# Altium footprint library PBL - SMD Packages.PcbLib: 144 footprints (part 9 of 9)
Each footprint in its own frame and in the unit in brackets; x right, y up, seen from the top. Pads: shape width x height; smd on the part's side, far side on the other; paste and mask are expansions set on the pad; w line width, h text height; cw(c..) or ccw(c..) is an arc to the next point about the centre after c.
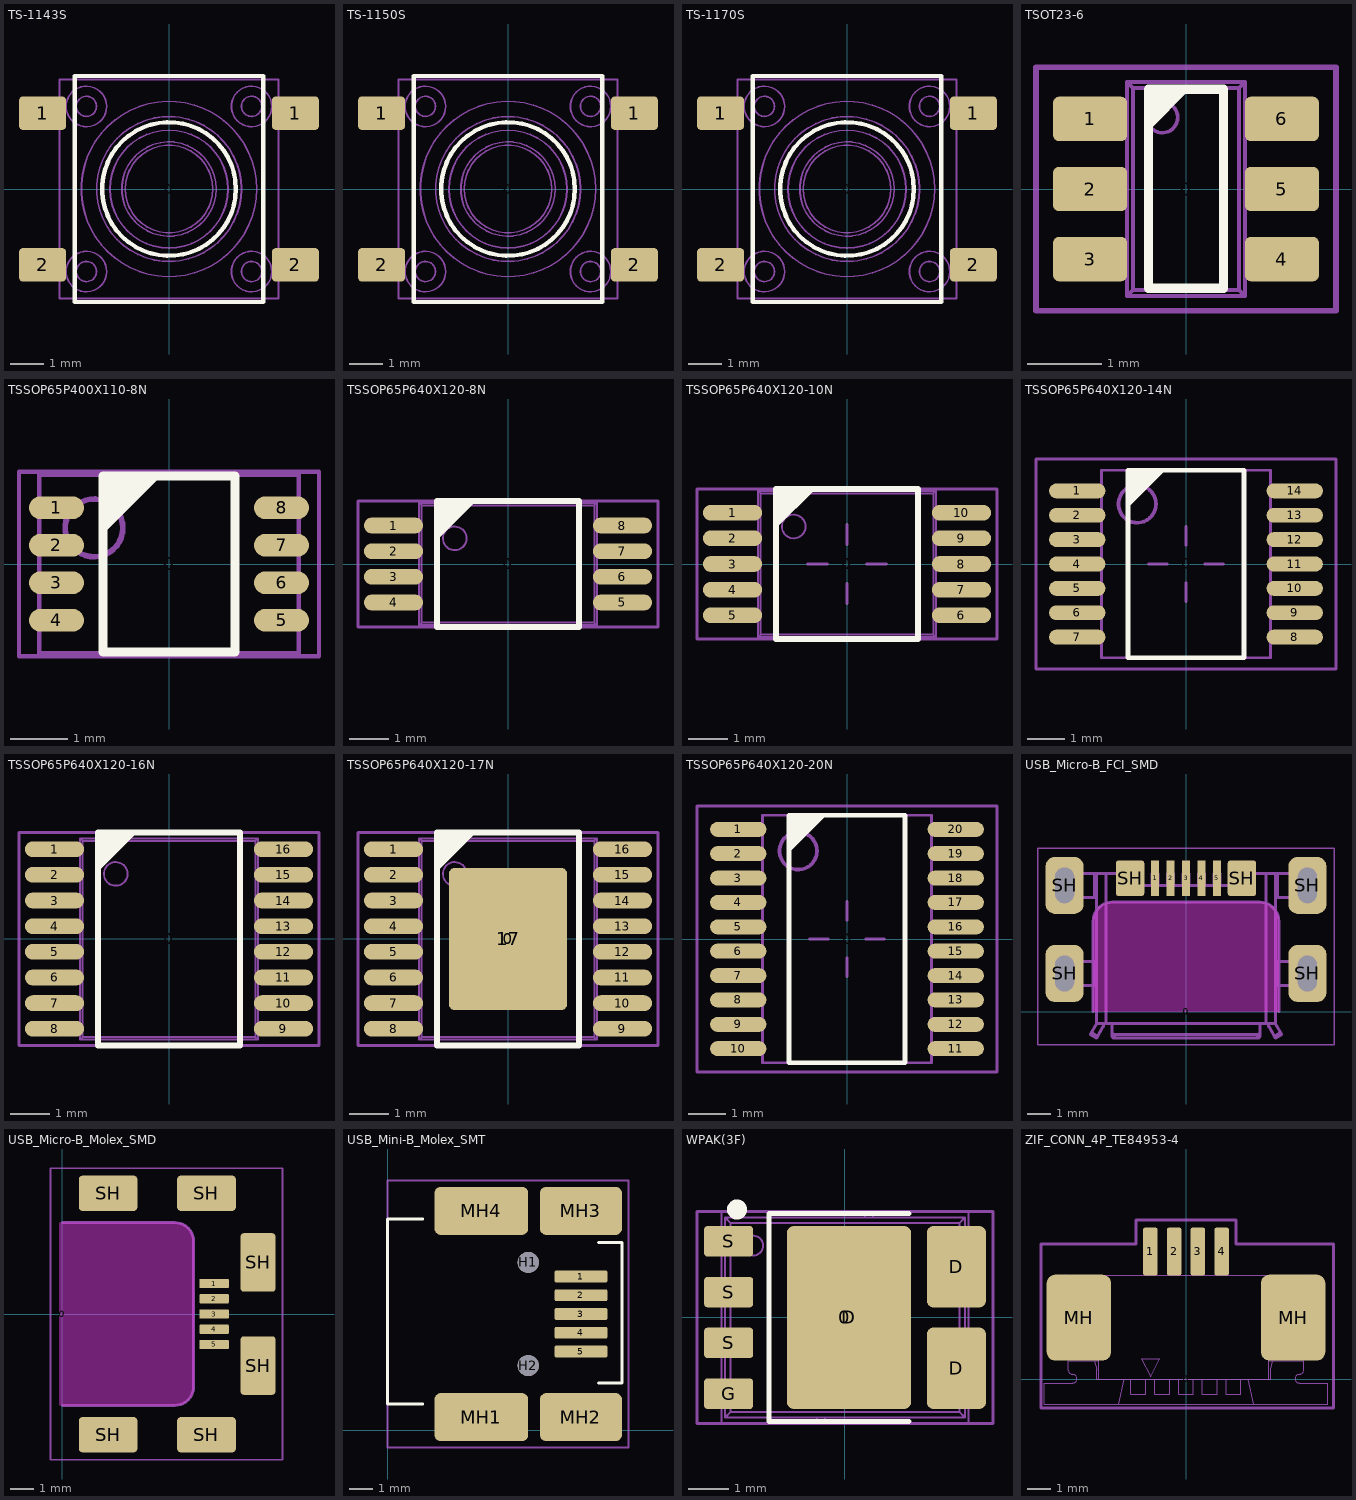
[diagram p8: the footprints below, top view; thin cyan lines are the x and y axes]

## TS-1143S [mm] "6.5x6.5mm SMD tact switch 4.3mm stem"
height 4.3
pads (5):
  round 0.508 on Mech15: 0(0,0)
  rrect25% 1.4x1 smd: 1(-3.75,2.25) 1(3.75,2.25) 2(-3.75,-2.25) 2(3.75,-2.25)
Top Overlay:
  circle w0.127: c0,0 r1.984
  lines w0.127: -2.794,-3.35 -2.794,3.35 2.794,3.35 2.794,-3.35 -2.794,-3.35
13 - 3D Top Side:
  circle w0.05: c0,0 r1.4
  circle w0.05: c0,0 r1.3
  circle w0.05: c0,-0.002 r1.75
  circle w0.05: c0,0 r2.15
  circle w0.05: c0,0 r2.6
  circle w0.05: c2.45,2.452 r0.3
  circle w0.05: c-2.45,2.452 r0.3
  circle w0.05: c2.45,-2.448 r0.3
  circle w0.05: c-2.45,-2.448 r0.3
  circle w0.05: c-2.45,2.45 r0.6
  circle w0.05: c2.45,2.45 r0.6
  circle w0.05: c2.45,-2.45 r0.6
  circle w0.05: c-2.45,-2.45 r0.6
  lines w0.05: -3.591,-2.6 -3.591,-1.9 ; -3.591,1.9 -3.591,2.6 ; -3.571,-2.6 -3.571,-1.9 ; -3.571,1.9 -3.571,2.6 ; -3.468,-2.6 -3.468,-1.9 ; -3.468,1.9 -3.468,2.6 ; -3.253,-2.6 -3.253,-1.9 ; -3.253,1.9 -3.253,2.6 ; -3.25,-2.6 -4,-2.6 -4,-1.9 -3.25,-1.9 ; -3.25,1.9 -4,1.9 -4,2.6 -3.25,2.6 ; 3.25,-2.6 4,-2.6 4,-1.9 3.25,-1.9 ; 3.25,1.9 4,1.9 4,2.6 3.25,2.6 ; 3.253,-2.6 3.253,-1.9 ; 3.253,1.9 3.253,2.6 ; 3.468,-2.6 3.468,-1.9 ; 3.468,1.9 3.468,2.6 ; 3.571,-2.6 3.571,-1.9 ; 3.571,1.9 3.571,2.6 ; 3.591,-2.6 3.591,-1.9 ; 3.591,1.9 3.591,2.6 ; -3.25,-3.25 3.25,-3.25 3.25,3.25 -3.25,3.25 -3.25,-3.25
3D body "TS-1143S-WP.STEP": height 4.3, standoff 0, extent -4,-3.25 4,3.25

## TS-1150S [mm] "6.5x6.5mm SMD tact switch 5.0mm stem"
height 5
pads (5):
  round 0.508 on Mech15: 0(0,0)
  rrect25% 1.4x1 smd: 1(-3.75,2.25) 1(3.75,2.25) 2(-3.75,-2.25) 2(3.75,-2.25)
Top Overlay:
  circle w0.127: c0,0 r1.984
  lines w0.127: -2.794,-3.35 -2.794,3.35 2.794,3.35 2.794,-3.35 -2.794,-3.35
13 - 3D Top Side:
  circle w0.05: c0,0 r1.4
  circle w0.05: c0,0 r1.3
  circle w0.05: c0,-0.002 r1.75
  circle w0.05: c0,0 r2.15
  circle w0.05: c0,0 r2.6
  circle w0.05: c2.45,2.452 r0.3
  circle w0.05: c-2.45,2.452 r0.3
  circle w0.05: c2.45,-2.448 r0.3
  circle w0.05: c-2.45,-2.448 r0.3
  circle w0.05: c-2.45,2.45 r0.6
  circle w0.05: c2.45,2.45 r0.6
  circle w0.05: c2.45,-2.45 r0.6
  circle w0.05: c-2.45,-2.45 r0.6
  lines w0.05: -3.591,-2.6 -3.591,-1.9 ; -3.591,1.9 -3.591,2.6 ; -3.571,-2.6 -3.571,-1.9 ; -3.571,1.9 -3.571,2.6 ; -3.468,-2.6 -3.468,-1.9 ; -3.468,1.9 -3.468,2.6 ; -3.253,-2.6 -3.253,-1.9 ; -3.253,1.9 -3.253,2.6 ; -3.25,-2.6 -4,-2.6 -4,-1.9 -3.25,-1.9 ; -3.25,1.9 -4,1.9 -4,2.6 -3.25,2.6 ; 3.25,-2.6 4,-2.6 4,-1.9 3.25,-1.9 ; 3.25,1.9 4,1.9 4,2.6 3.25,2.6 ; 3.253,-2.6 3.253,-1.9 ; 3.253,1.9 3.253,2.6 ; 3.468,-2.6 3.468,-1.9 ; 3.468,1.9 3.468,2.6 ; 3.571,-2.6 3.571,-1.9 ; 3.571,1.9 3.571,2.6 ; 3.591,-2.6 3.591,-1.9 ; 3.591,1.9 3.591,2.6 ; -3.25,-3.25 3.25,-3.25 3.25,3.25 -3.25,3.25 -3.25,-3.25
3D body "TS-1150S-WP.STEP": height 5, standoff 0, extent -4,-3.25 4,3.25

## TS-1170S [mm] "6.5x6.5mm SMD tact switch 7.0mm stem"
height 7
pads (5):
  round 0.508 on Mech15: 0(0,0)
  rrect25% 1.4x1 smd: 1(-3.75,2.25) 1(3.75,2.25) 2(-3.75,-2.25) 2(3.75,-2.25)
Top Overlay:
  circle w0.127: c0,0 r1.984
  lines w0.127: -2.794,-3.35 -2.794,3.35 2.794,3.35 2.794,-3.35 -2.794,-3.35
13 - 3D Top Side:
  circle w0.05: c-2.45,-2.45 r0.6
  circle w0.05: c2.45,-2.45 r0.6
  circle w0.05: c2.45,2.45 r0.6
  circle w0.05: c-2.45,2.45 r0.6
  circle w0.05: c-2.45,-2.448 r0.3
  circle w0.05: c2.45,-2.448 r0.3
  circle w0.05: c-2.45,2.452 r0.3
  circle w0.05: c2.45,2.452 r0.3
  circle w0.05: c0,0 r2.6
  circle w0.05: c0,0 r2.15
  circle w0.05: c0,-0.002 r1.75
  circle w0.05: c0,0 r1.3
  circle w0.05: c0,0 r1.4
  lines w0.05: -3.591,-2.6 -3.591,-1.9 ; -3.591,1.9 -3.591,2.6 ; -3.571,-2.6 -3.571,-1.9 ; -3.571,1.9 -3.571,2.6 ; -3.468,-2.6 -3.468,-1.9 ; -3.468,1.9 -3.468,2.6 ; -3.253,-2.6 -3.253,-1.9 ; -3.253,1.9 -3.253,2.6 ; -3.25,-2.6 -4,-2.6 -4,-1.9 -3.25,-1.9 ; -3.25,1.9 -4,1.9 -4,2.6 -3.25,2.6 ; 3.25,-2.6 4,-2.6 4,-1.9 3.25,-1.9 ; 3.25,1.9 4,1.9 4,2.6 3.25,2.6 ; 3.253,-2.6 3.253,-1.9 ; 3.253,1.9 3.253,2.6 ; 3.468,-2.6 3.468,-1.9 ; 3.468,1.9 3.468,2.6 ; 3.571,-2.6 3.571,-1.9 ; 3.571,1.9 3.571,2.6 ; 3.591,-2.6 3.591,-1.9 ; 3.591,1.9 3.591,2.6 ; -3.25,-3.25 -3.25,3.25 3.25,3.25 3.25,-3.25 -3.25,-3.25
3D body "TS-1170S-WP.stp": height 7, standoff 0, extent -4,-3.25 4,3.25

## TSOT23-6 [mm] "SOT-23-6 Thin, 6 lead"
height 1
pads (7):
  round 0.5 on Mech15: 0(0,0)
  rrect25% 1x0.6 smd: 1(-1.3,0.95) 2(-1.3,0) 3(-1.3,-0.95) 4(1.3,-0.95) 5(1.3,0) 6(1.3,0.95)
Top Overlay:
  region: -0.508,1.353 0.053,1.353 -0.508,0.792
  lines w0.127: -0.508,-1.347 0.508,-1.347 0.508,1.353 -0.508,1.353 -0.508,-1.347
  text "." at -2.275,0.95 h0.1
13 - 3D Top Side:
  circle w0.05: c-0.32,0.97 r0.208
  lines w0.05: -1.191,-1.15 -1.191,-0.75 ; -1.191,-0.2 -1.191,0.2 ; -1.191,0.75 -1.191,1.15 ; -1.1,-1.15 -1.1,-0.75 ; -1.1,-0.2 -1.1,0.2 ; -1.1,0.75 -1.1,1.15 ; -1.094,-1.15 -1.094,-0.75 ; -1.094,-0.2 -1.094,0.2 ; -1.094,0.75 -1.094,1.15 ; -0.844,-1.15 -0.844,-0.75 ; -0.844,-0.2 -0.844,0.2 ; -0.844,0.75 -0.844,1.15 ; -0.8,-1.15 -1.4,-1.15 -1.4,-0.75 -0.8,-0.75 ; -0.8,-0.2 -1.4,-0.2 -1.4,0.2 -0.8,0.2 ; -0.8,0.75 -1.4,0.75 -1.4,1.15 -0.8,1.15 ; 0.8,-1.15 1.4,-1.15 1.4,-0.75 0.8,-0.75 ; 0.8,-0.2 1.4,-0.2 1.4,0.2 0.8,0.2 ; 0.8,0.75 1.4,0.75 1.4,1.15 0.8,1.15 ; 0.844,-1.15 0.844,-0.75 ; 0.844,-0.2 0.844,0.2 ; 0.844,0.75 0.844,1.15 ; 1.094,-1.15 1.094,-0.75 ; 1.094,-0.2 1.094,0.2 ; 1.094,0.75 1.094,1.15 ; 1.1,-1.15 1.1,-0.75 ; 1.1,-0.2 1.1,0.2 ; 1.1,0.75 1.1,1.15 ; 1.191,-1.15 1.191,-0.75 ; 1.191,-0.2 1.191,0.2 ; 1.191,0.75 1.191,1.15 ; -0.8,-1.45 -0.8,1.45 ; -0.8,-1.45 -0.719,-1.369 ; -0.8,-1.45 0.8,-1.45 ; -0.8,1.45 -0.719,1.369 ; -0.8,1.45 0.8,1.45 ; -0.719,-1.369 0.719,-1.369 ; -0.719,-1.369 -0.719,1.369 ; -0.719,1.369 0.719,1.369 ; 0.719,-1.369 0.8,-1.45 ; 0.719,-1.369 0.719,1.369 ; 0.719,1.369 0.8,1.45 ; 0.8,-1.45 0.8,1.45
15 - Top Courtyards:
  lines w0.076: -2.032,-1.651 2.032,-1.651 2.032,1.651 -2.032,1.651 -2.032,-1.651
3D body "TSOT23-6.STEP": height 1, standoff 0, extent -1.4,-1.45 1.4,1.45

## TSSOP65P400X110-8N [mm] "TSSOP, 8 Leads, Body 3.1x3.1mm (max), lead span 4.0mm, Pitch 0.65mm, IPC Medium Density"
height 1.1
pads (9):
  round 0.508 on Mech15: 0(0,0)
  oval 0.95x0.396 smd paste-0.051: 1(-1.95,0.975) 2(-1.95,0.325) 3(-1.95,-0.325) 4(-1.95,-0.975) 5(1.95,-0.975) 6(1.95,-0.325) 7(1.95,0.325) 8(1.95,0.975)
Top Overlay:
  region: -1.143,1.524 -0.143,1.524 -1.143,0.524
  lines w0.152: -1.143,-1.524 1.143,-1.524 1.143,1.524 -1.143,1.524 -1.143,-1.524
  text "." at -1.925,1.65 h0.1
Top Solder:
  rectangle: -2.3,-1.016 -1.6,1.016
  region: 2.3,1.016 1.6,1.016 1.6,-1.016 2.3,-1.016
13 - 3D Top Side:
  circle w0.1: c-1.3,0.625 r0.5
  lines w0.076: -2.25,-1.55 2.25,-1.55 2.25,1.55 -2.25,1.55 -2.25,-1.55
15 - Top Courtyards:
  lines w0.076: -2.6,-1.6 2.6,-1.6 2.6,1.6 -2.6,1.6 -2.6,-1.6
3D body "TSSOP65P400X110-8.STEP": height 1.09, standoff -0.01, extent -2.05,-1.55 2.05,1.55

## TSSOP65P640X120-8N [mm] "TSSOP, 8 Leads, Body 3.1x4.5mm (max), Pitch 0.65mm, IPC Medium Density"
height 1.2
pads (9):
  round 0.508 on Mech15: 0(0,0)
  oval 1.5x0.4 smd paste-0.051: 1(-2.9,0.975) 2(-2.9,0.325) 3(-2.9,-0.325) 4(-2.9,-0.975) 5(2.9,-0.975) 6(2.9,-0.325) 7(2.9,0.325) 8(2.9,0.975)
Top Overlay:
  region: -1.8,1.6 -0.8,1.6 -1.8,0.6
  lines w0.152: -1.8,-1.6 -1.8,1.6 1.8,1.6 1.8,-1.6 -1.8,-1.6
  text "." at -2.85,1.7 h0.1
Top Solder:
  rectangle: -3.5,-1.016 -2.3,1.016
  region: 3.5,1.016 2.3,1.016 2.3,-1.016 3.5,-1.016
13 - 3D Top Side:
  circle w0.05: c-1.35,0.65 r0.3
  lines w0.05: -2.839,-1.125 -2.839,-0.825 ; -2.839,-0.475 -2.839,-0.175 ; -2.839,0.175 -2.839,0.475 ; -2.839,0.825 -2.839,1.125 ; -2.795,-1.125 -2.795,-0.825 ; -2.795,-0.475 -2.795,-0.175 ; -2.795,0.175 -2.795,0.475 ; -2.795,0.825 -2.795,1.125 ; -2.693,-1.125 -2.693,-0.825 ; -2.693,-0.475 -2.693,-0.175 ; -2.693,0.175 -2.693,0.475 ; -2.693,0.825 -2.693,1.125 ; -2.5,-1.125 -2.5,-0.825 ; -2.5,-0.475 -2.5,-0.175 ; -2.5,0.175 -2.5,0.475 ; -2.5,0.825 -2.5,1.125 ; -2.25,-1.125 -3.25,-1.125 -3.25,-0.825 -2.25,-0.825 ; -2.25,-0.475 -3.25,-0.475 -3.25,-0.175 -2.25,-0.175 ; -2.25,0.175 -3.25,0.175 -3.25,0.475 -2.25,0.475 ; -2.25,0.825 -3.25,0.825 -3.25,1.125 -2.25,1.125 ; 2.25,-1.125 3.25,-1.125 3.25,-0.825 2.25,-0.825 ; 2.25,-0.475 3.25,-0.475 3.25,-0.175 2.25,-0.175 ; 2.25,0.175 3.25,0.175 3.25,0.475 2.25,0.475 ; 2.25,0.825 3.25,0.825 3.25,1.125 2.25,1.125 ; 2.5,-1.125 2.5,-0.825 ; 2.5,-0.475 2.5,-0.175 ; 2.5,0.175 2.5,0.475 ; 2.5,0.825 2.5,1.125 ; 2.693,-1.125 2.693,-0.825 ; 2.693,-0.475 2.693,-0.175 ; 2.693,0.175 2.693,0.475 ; 2.693,0.825 2.693,1.125 ; 2.795,-1.125 2.795,-0.825 ; 2.795,-0.475 2.795,-0.175 ; 2.795,0.175 2.795,0.475 ; 2.795,0.825 2.795,1.125 ; 2.839,-1.125 2.839,-0.825 ; 2.839,-0.475 2.839,-0.175 ; 2.839,0.175 2.839,0.475 ; 2.839,0.825 2.839,1.125 ; -2.25,-1.55 -2.25,1.55 ; -2.25,-1.55 -2.187,-1.487 ; -2.25,-1.55 2.25,-1.55 ; -2.25,1.55 2.25,1.55 ; -2.25,1.55 -2.187,1.487 ; -2.187,-1.487 -2.187,1.487 ; -2.187,-1.487 2.187,-1.487 ; -2.187,1.487 2.187,1.487 ; 2.187,-1.487 2.187,1.487 ; 2.187,-1.487 2.25,-1.55 ; 2.187,1.487 2.25,1.55 ; 2.25,-1.55 2.25,1.55
15 - Top Courtyards:
  lines w0.076: -3.8,-1.6 -3.8,1.6 3.8,1.6 3.8,-1.6 -3.8,-1.6
3D body "TSSOP-8.STEP": height 1.19, standoff -0.01, extent -3.25,-1.55 3.25,1.55

## TSSOP65P640X120-10N [mm] "TSSOP, 10 Leads, Body 3.7x4.5mm (max), Pitch 0.65mm, IPC Medium Density"
height 1.2
pads (11):
  round 0.508 on Mech15: 0(0,0)
  oval 1.5x0.4 smd paste-0.051: 1(-2.9,1.3) 2(-2.9,0.65) 3(-2.9,0) 4(-2.9,-0.65) 5(-2.9,-1.3) 6(2.9,-1.3) 7(2.9,-0.65) 8(2.9,0) 9(2.9,0.65) 10(2.9,1.3)
Top Overlay:
  region: -1.8,1.9 -0.8,1.9 -1.8,0.9
  lines w0.152: -1.8,-1.9 -1.8,1.9 1.8,1.9 1.8,-1.9 -1.8,-1.9
  text "." at -2.85,2.025 h0.1
Top Solder:
  rectangle: -3.5,-1.3 -2.3,1.3
  region: 3.5,1.3 2.3,1.3 2.3,-1.3 3.5,-1.3
13 - 3D Top Side:
  circle w0.05: c-1.35,0.95 r0.3
  lines w0.05: -2.839,-1.45 -2.839,-1.15 ; -2.839,-0.8 -2.839,-0.5 ; -2.839,-0.15 -2.839,0.15 ; -2.839,0.5 -2.839,0.8 ; -2.839,1.15 -2.839,1.45 ; -2.795,-1.45 -2.795,-1.15 ; -2.795,-0.8 -2.795,-0.5 ; -2.795,-0.15 -2.795,0.15 ; -2.795,0.5 -2.795,0.8 ; -2.795,1.15 -2.795,1.45 ; -2.693,-1.45 -2.693,-1.15 ; -2.693,-0.8 -2.693,-0.5 ; -2.693,-0.15 -2.693,0.15 ; -2.693,0.5 -2.693,0.8 ; -2.693,1.15 -2.693,1.45 ; -2.5,-1.45 -2.5,-1.15 ; -2.5,-0.8 -2.5,-0.5 ; -2.5,-0.15 -2.5,0.15 ; -2.5,0.5 -2.5,0.8 ; -2.5,1.15 -2.5,1.45 ; -2.25,-1.45 -3.25,-1.45 -3.25,-1.15 -2.25,-1.15 ; -2.25,-0.8 -3.25,-0.8 -3.25,-0.5 -2.25,-0.5 ; -2.25,-0.15 -3.25,-0.15 -3.25,0.15 -2.25,0.15 ; -2.25,0.5 -3.25,0.5 -3.25,0.8 -2.25,0.8 ; -2.25,1.15 -3.25,1.15 -3.25,1.45 -2.25,1.45 ; 2.25,-1.45 3.25,-1.45 3.25,-1.15 2.25,-1.15 ; 2.25,-0.8 3.25,-0.8 3.25,-0.5 2.25,-0.5 ; 2.25,-0.15 3.25,-0.15 3.25,0.15 2.25,0.15 ; 2.25,0.5 3.25,0.5 3.25,0.8 2.25,0.8 ; 2.25,1.15 3.25,1.15 3.25,1.45 2.25,1.45 ; 2.5,-1.45 2.5,-1.15 ; 2.5,-0.8 2.5,-0.5 ; 2.5,-0.15 2.5,0.15 ; 2.5,0.5 2.5,0.8 ; 2.5,1.15 2.5,1.45 ; 2.693,-1.45 2.693,-1.15 ; 2.693,-0.8 2.693,-0.5 ; 2.693,-0.15 2.693,0.15 ; 2.693,0.5 2.693,0.8 ; 2.693,1.15 2.693,1.45 ; 2.795,-1.45 2.795,-1.15 ; 2.795,-0.8 2.795,-0.5 ; 2.795,-0.15 2.795,0.15 ; 2.795,0.5 2.795,0.8 ; 2.795,1.15 2.795,1.45 ; 2.839,-1.45 2.839,-1.15 ; 2.839,-0.8 2.839,-0.5 ; 2.839,-0.15 2.839,0.15 ; 2.839,0.5 2.839,0.8 ; 2.839,1.15 2.839,1.45 ; -2.25,-1.85 -2.25,1.85 ; -2.25,-1.85 -2.187,-1.787 ; -2.25,-1.85 2.25,-1.85 ; -2.25,1.85 2.25,1.85 ; -2.25,1.85 -2.187,1.787 ; -2.187,-1.787 -2.187,1.787 ; -2.187,-1.787 2.187,-1.787 ; -2.187,1.787 2.187,1.787 ; 2.187,-1.787 2.187,1.787 ; 2.187,-1.787 2.25,-1.85 ; 2.187,1.787 2.25,1.85 ; 2.25,-1.85 2.25,1.85
15 - Top Courtyards:
  lines w0.076: -1,0 -0.5,0 ; 0,-1 0,-0.5 ; 0,0.5 0,1 ; 0.5,0 1,0 ; -3.8,-1.9 -3.8,1.9 3.8,1.9 3.8,-1.9 -3.8,-1.9
3D body "TSSOP65P640X120-10N.STEP": height 1.2, standoff 0, extent -3.25,-1.85 3.25,1.85

## TSSOP65P640X120-14N [mm] "TSSOP, 14-Leads, Body 5.0x4.5mm (max), Pitch 0.65mm, IPC Medium Density"
height 1.2
pads (15):
  round 0.508 on Mech15: 0(0,0)
  oval 1.5x0.4 smd paste-1: 1(-2.9,1.95) 2(-2.9,1.3) 3(-2.9,0.65) 4(-2.9,0) 5(-2.9,-0.65) 6(-2.9,-1.3) 7(-2.9,-1.95) 8(2.9,-1.95) 9(2.9,-1.3) 10(2.9,-0.65) 11(2.9,0) 12(2.9,0.65) 13(2.9,1.3) 14(2.9,1.95)
Top Overlay:
  region: -1.55,2.5 -0.55,2.5 -1.55,1.5
  lines w0.127: -1.55,-2.5 -1.55,2.5 1.55,2.5 1.55,-2.5 -1.55,-2.5
  text "." at -2.9,2.725 h0.1
Top Paste:
  region: 3.5,-1.8 2.3,-1.8 2.3,-2.1 3.5,-2.1
  region: 3.5,-1.15 2.3,-1.15 2.3,-1.45 3.5,-1.45
  region: 3.5,-0.5 2.3,-0.5 2.3,-0.8 3.5,-0.8
  region: 3.5,0.15 2.3,0.15 2.3,-0.15 3.5,-0.15
  region: 3.5,0.8 2.3,0.8 2.3,0.5 3.5,0.5
  region: 3.5,1.45 2.3,1.45 2.3,1.15 3.5,1.15
  region: 3.5,2.1 2.3,2.1 2.3,1.8 3.5,1.8
  rectangle: -3.5,1.8 -2.3,2.1
  rectangle: -3.5,1.15 -2.3,1.45
  rectangle: -3.5,0.5 -2.3,0.8
  rectangle: -3.5,-0.15 -2.3,0.15
  rectangle: -3.5,-0.8 -2.3,-0.5
  rectangle: -3.5,-1.45 -2.3,-1.15
  rectangle: -3.5,-2.1 -2.3,-1.8
08 - Top ASM Des:
  text ".Designator" at -0.375,2.45 h2
13 - 3D Top Side:
  circle w0.1: c-1.3,1.6 r0.5
  lines w0.076: -2.25,-2.5 -2.25,2.5 2.25,2.5 2.25,-2.5 -2.25,-2.5
15 - Top Courtyards:
  lines w0.076: -1,0 -0.5,0 ; 0,-1 0,-0.5 ; 0,0.5 0,1 ; 0.5,0 1,0 ; -4,-2.8 -4,2.8 4,2.8 4,-2.8 -4,-2.8
3D body "SOP65P640X120-14N.stp": height 1.05, standoff 0, extent -3.205,-2.5 3.205,2.5

## TSSOP65P640X120-16N [mm] "TSSOP, 16 Leads, Body 5.1x4.5mm (max), Pitch 0.65mm, IPC Medium Density"
height 1.2
pads (17):
  round 0.508 on Mech15: 0(0,0)
  oval 1.5x0.4 smd paste-0.051: 1(-2.9,2.275) 2(-2.9,1.625) 3(-2.9,0.975) 4(-2.9,0.325) 5(-2.9,-0.325) 6(-2.9,-0.975) 7(-2.9,-1.625) 8(-2.9,-2.275) 9(2.9,-2.275) 10(2.9,-1.625) 11(2.9,-0.975) 12(2.9,-0.325) 13(2.9,0.325) 14(2.9,0.975) 15(2.9,1.625) 16(2.9,2.275)
Top Overlay:
  region: -1.8,2.7 -0.8,2.7 -1.8,1.7
  lines w0.152: -1.8,-2.7 -1.8,2.7 1.8,2.7 1.8,-2.7 -1.8,-2.7
  text "." at -2.85,3 h0.1
Top Solder:
  rectangle: -3.5,-2.4 -2.3,2.4
  region: 3.5,2.4 2.3,2.4 2.3,-2.4 3.5,-2.4
13 - 3D Top Side:
  circle w0.05: c-1.35,1.65 r0.3
  lines w0.05: -2.839,-2.425 -2.839,-2.125 ; -2.839,-1.775 -2.839,-1.475 ; -2.839,-1.125 -2.839,-0.825 ; -2.839,-0.475 -2.839,-0.175 ; -2.839,0.175 -2.839,0.475 ; -2.839,0.825 -2.839,1.125 ; -2.839,1.475 -2.839,1.775 ; -2.839,2.125 -2.839,2.425 ; -2.795,-2.425 -2.795,-2.125 ; -2.795,-1.775 -2.795,-1.475 ; -2.795,-1.125 -2.795,-0.825 ; -2.795,-0.475 -2.795,-0.175 ; -2.795,0.175 -2.795,0.475 ; -2.795,0.825 -2.795,1.125 ; -2.795,1.475 -2.795,1.775 ; -2.795,2.125 -2.795,2.425 ; -2.693,-2.425 -2.693,-2.125 ; -2.693,-1.775 -2.693,-1.475 ; -2.693,-1.125 -2.693,-0.825 ; -2.693,-0.475 -2.693,-0.175 ; -2.693,0.175 -2.693,0.475 ; -2.693,0.825 -2.693,1.125 ; -2.693,1.475 -2.693,1.775 ; -2.693,2.125 -2.693,2.425 ; -2.5,-2.425 -2.5,-2.125 ; -2.5,-1.775 -2.5,-1.475 ; -2.5,-1.125 -2.5,-0.825 ; -2.5,-0.475 -2.5,-0.175 ; -2.5,0.175 -2.5,0.475 ; -2.5,0.825 -2.5,1.125 ; -2.5,1.475 -2.5,1.775 ; -2.5,2.125 -2.5,2.425 ; -2.25,-2.425 -3.25,-2.425 -3.25,-2.125 -2.25,-2.125 ; -2.25,-1.775 -3.25,-1.775 -3.25,-1.475 -2.25,-1.475 ; -2.25,-1.125 -3.25,-1.125 -3.25,-0.825 -2.25,-0.825 ; -2.25,-0.475 -3.25,-0.475 -3.25,-0.175 -2.25,-0.175 ; -2.25,0.175 -3.25,0.175 -3.25,0.475 -2.25,0.475 ; -2.25,0.825 -3.25,0.825 -3.25,1.125 -2.25,1.125 ; -2.25,1.475 -3.25,1.475 -3.25,1.775 -2.25,1.775 ; -2.25,2.125 -3.25,2.125 -3.25,2.425 -2.25,2.425 ; 2.25,-2.425 3.25,-2.425 3.25,-2.125 2.25,-2.125 ; 2.25,-1.775 3.25,-1.775 3.25,-1.475 2.25,-1.475 ; 2.25,-1.125 3.25,-1.125 3.25,-0.825 2.25,-0.825 ; 2.25,-0.475 3.25,-0.475 3.25,-0.175 2.25,-0.175 ; 2.25,0.175 3.25,0.175 3.25,0.475 2.25,0.475 ; 2.25,0.825 3.25,0.825 3.25,1.125 2.25,1.125 ; 2.25,1.475 3.25,1.475 3.25,1.775 2.25,1.775 ; 2.25,2.125 3.25,2.125 3.25,2.425 2.25,2.425 ; 2.5,-2.425 2.5,-2.125 ; 2.5,-1.775 2.5,-1.475 ; 2.5,-1.125 2.5,-0.825 ; 2.5,-0.475 2.5,-0.175 ; 2.5,0.175 2.5,0.475 ; 2.5,0.825 2.5,1.125 ; 2.5,1.475 2.5,1.775 ; 2.5,2.125 2.5,2.425 ; 2.693,-2.425 2.693,-2.125 ; 2.693,-1.775 2.693,-1.475 ; 2.693,-1.125 2.693,-0.825 ; 2.693,-0.475 2.693,-0.175 ; 2.693,0.175 2.693,0.475 ; 2.693,0.825 2.693,1.125 ; 2.693,1.475 2.693,1.775 ; 2.693,2.125 2.693,2.425 ; 2.795,-2.425 2.795,-2.125 ; 2.795,-1.775 2.795,-1.475 ; 2.795,-1.125 2.795,-0.825 ; 2.795,-0.475 2.795,-0.175 ; 2.795,0.175 2.795,0.475 ; 2.795,0.825 2.795,1.125 ; 2.795,1.475 2.795,1.775 ; 2.795,2.125 2.795,2.425 ; 2.839,-2.425 2.839,-2.125 ; 2.839,-1.775 2.839,-1.475 ; 2.839,-1.125 2.839,-0.825 ; 2.839,-0.475 2.839,-0.175 ; 2.839,0.175 2.839,0.475 ; 2.839,0.825 2.839,1.125 ; 2.839,1.475 2.839,1.775 ; 2.839,2.125 2.839,2.425 ; -2.25,-2.55 -2.25,2.55 ; -2.25,-2.55 -2.187,-2.487 ; -2.25,-2.55 2.25,-2.55 ; -2.25,2.55 2.25,2.55 ; -2.25,2.55 -2.187,2.487 ; -2.187,-2.487 -2.187,2.487 ; -2.187,-2.487 2.187,-2.487 ; -2.187,2.487 2.187,2.487 ; 2.187,-2.487 2.187,2.487 ; 2.187,-2.487 2.25,-2.55 ; 2.187,2.487 2.25,2.55 ; 2.25,-2.55 2.25,2.55
15 - Top Courtyards:
  lines w0.076: -3.8,-2.7 -3.8,2.7 3.8,2.7 3.8,-2.7 -3.8,-2.7
3D body "TSSOP65P640X120-16N.STEP": height 1.2, standoff 0, extent -3.25,-2.55 3.25,2.55

## TSSOP65P640X120-17N [mm] "TSSOP, 16 Leads with exposed body pad, Body 5.1x4.5mm (max), Pitch 0.65mm, IPC Medium Density"
height 1.2
pads (18):
  round 0.508 on Mech15: 0(0,0)
  oval 1.5x0.4 smd paste-0.051: 1(-2.9,2.275) 2(-2.9,1.625) 3(-2.9,0.975) 4(-2.9,0.325) 5(-2.9,-0.325) 6(-2.9,-0.975) 7(-2.9,-1.625) 8(-2.9,-2.275) 9(2.9,-2.275) 10(2.9,-1.625) 11(2.9,-0.975) 12(2.9,-0.325) 13(2.9,0.325) 14(2.9,0.975) 15(2.9,1.625) 16(2.9,2.275)
  rrect10% 3x3.6 smd paste-0.051: 17(0,0)
Top Overlay:
  region: -1.8,2.7 -0.8,2.7 -1.8,1.7
  lines w0.152: -1.8,-2.7 1.8,-2.7 1.8,2.7 -1.8,2.7 -1.8,-2.7
  text "." at -2.85,3 h0.1
Top Solder:
  region: 3.5,2.4 2.3,2.4 2.3,-2.4 3.5,-2.4
  rectangle: -3.5,-2.4 -2.3,2.4
13 - 3D Top Side:
  circle w0.05: c-1.35,1.65 r0.3
  lines w0.05: -2.839,-2.425 -2.839,-2.125 ; -2.839,-1.775 -2.839,-1.475 ; -2.839,-1.125 -2.839,-0.825 ; -2.839,-0.475 -2.839,-0.175 ; -2.839,0.175 -2.839,0.475 ; -2.839,0.825 -2.839,1.125 ; -2.839,1.475 -2.839,1.775 ; -2.839,2.125 -2.839,2.425 ; -2.795,-2.425 -2.795,-2.125 ; -2.795,-1.775 -2.795,-1.475 ; -2.795,-1.125 -2.795,-0.825 ; -2.795,-0.475 -2.795,-0.175 ; -2.795,0.175 -2.795,0.475 ; -2.795,0.825 -2.795,1.125 ; -2.795,1.475 -2.795,1.775 ; -2.795,2.125 -2.795,2.425 ; -2.693,-2.425 -2.693,-2.125 ; -2.693,-1.775 -2.693,-1.475 ; -2.693,-1.125 -2.693,-0.825 ; -2.693,-0.475 -2.693,-0.175 ; -2.693,0.175 -2.693,0.475 ; -2.693,0.825 -2.693,1.125 ; -2.693,1.475 -2.693,1.775 ; -2.693,2.125 -2.693,2.425 ; -2.5,-2.425 -2.5,-2.125 ; -2.5,-1.775 -2.5,-1.475 ; -2.5,-1.125 -2.5,-0.825 ; -2.5,-0.475 -2.5,-0.175 ; -2.5,0.175 -2.5,0.475 ; -2.5,0.825 -2.5,1.125 ; -2.5,1.475 -2.5,1.775 ; -2.5,2.125 -2.5,2.425 ; -2.25,-2.425 -3.25,-2.425 -3.25,-2.125 -2.25,-2.125 ; -2.25,-1.775 -3.25,-1.775 -3.25,-1.475 -2.25,-1.475 ; -2.25,-1.125 -3.25,-1.125 -3.25,-0.825 -2.25,-0.825 ; -2.25,-0.475 -3.25,-0.475 -3.25,-0.175 -2.25,-0.175 ; -2.25,0.175 -3.25,0.175 -3.25,0.475 -2.25,0.475 ; -2.25,0.825 -3.25,0.825 -3.25,1.125 -2.25,1.125 ; -2.25,1.475 -3.25,1.475 -3.25,1.775 -2.25,1.775 ; -2.25,2.125 -3.25,2.125 -3.25,2.425 -2.25,2.425 ; 2.25,-2.425 3.25,-2.425 3.25,-2.125 2.25,-2.125 ; 2.25,-1.775 3.25,-1.775 3.25,-1.475 2.25,-1.475 ; 2.25,-1.125 3.25,-1.125 3.25,-0.825 2.25,-0.825 ; 2.25,-0.475 3.25,-0.475 3.25,-0.175 2.25,-0.175 ; 2.25,0.175 3.25,0.175 3.25,0.475 2.25,0.475 ; 2.25,0.825 3.25,0.825 3.25,1.125 2.25,1.125 ; 2.25,1.475 3.25,1.475 3.25,1.775 2.25,1.775 ; 2.25,2.125 3.25,2.125 3.25,2.425 2.25,2.425 ; 2.5,-2.425 2.5,-2.125 ; 2.5,-1.775 2.5,-1.475 ; 2.5,-1.125 2.5,-0.825 ; 2.5,-0.475 2.5,-0.175 ; 2.5,0.175 2.5,0.475 ; 2.5,0.825 2.5,1.125 ; 2.5,1.475 2.5,1.775 ; 2.5,2.125 2.5,2.425 ; 2.693,-2.425 2.693,-2.125 ; 2.693,-1.775 2.693,-1.475 ; 2.693,-1.125 2.693,-0.825 ; 2.693,-0.475 2.693,-0.175 ; 2.693,0.175 2.693,0.475 ; 2.693,0.825 2.693,1.125 ; 2.693,1.475 2.693,1.775 ; 2.693,2.125 2.693,2.425 ; 2.795,-2.425 2.795,-2.125 ; 2.795,-1.775 2.795,-1.475 ; 2.795,-1.125 2.795,-0.825 ; 2.795,-0.475 2.795,-0.175 ; 2.795,0.175 2.795,0.475 ; 2.795,0.825 2.795,1.125 ; 2.795,1.475 2.795,1.775 ; 2.795,2.125 2.795,2.425 ; 2.839,-2.425 2.839,-2.125 ; 2.839,-1.775 2.839,-1.475 ; 2.839,-1.125 2.839,-0.825 ; 2.839,-0.475 2.839,-0.175 ; 2.839,0.175 2.839,0.475 ; 2.839,0.825 2.839,1.125 ; 2.839,1.475 2.839,1.775 ; 2.839,2.125 2.839,2.425 ; -2.25,-2.55 2.25,-2.55 ; -2.25,-2.55 -2.187,-2.487 ; -2.25,-2.55 -2.25,2.55 ; -2.25,2.55 -2.187,2.487 ; -2.25,2.55 2.25,2.55 ; -2.187,-2.487 2.187,-2.487 ; -2.187,-2.487 -2.187,2.487 ; -2.187,2.487 2.187,2.487 ; 2.187,-2.487 2.25,-2.55 ; 2.187,-2.487 2.187,2.487 ; 2.187,2.487 2.25,2.55 ; 2.25,-2.55 2.25,2.55
15 - Top Courtyards:
  lines w0.076: -3.8,-2.7 3.8,-2.7 3.8,2.7 -3.8,2.7 -3.8,-2.7
3D body "TSSOP65P640X120-16N.STEP": height 1.2, standoff 0, extent -3.25,-2.55 3.25,2.55

## TSSOP65P640X120-20N [mm] "TSSOP, 20-Leads, Body 6.6x4.5mm (max), Pitch 0.65mm, IPC Medium Density"
height 1.2
pads (21):
  round 0.508 on Mech15 mask+0.127: 0(0,0)
  oval 1.5x0.4 smd paste-1 mask+0.127: 1(-2.9,2.925) 2(-2.9,2.275) 3(-2.9,1.625) 4(-2.9,0.975) 5(-2.9,0.325) 6(-2.9,-0.325) 7(-2.9,-0.975) 8(-2.9,-1.625) 9(-2.9,-2.275) 10(-2.9,-2.925) 11(2.9,-2.925) 12(2.9,-2.275) 13(2.9,-1.625) 14(2.9,-0.975) 15(2.9,-0.325) 16(2.9,0.325) 17(2.9,0.975) 18(2.9,1.625) 19(2.9,2.275) 20(2.9,2.925)
Top Overlay:
  region: -1.55,3.3 -0.55,3.3 -1.55,2.3
  lines w0.127: -1.55,-3.3 1.55,-3.3 1.55,3.3 -1.55,3.3 -1.55,-3.3
  text "." at -2.85,3.7 h0.1
Top Paste:
  region: 3.5,-2.775 2.3,-2.775 2.3,-3.075 3.5,-3.075
  region: 3.5,-2.125 2.3,-2.125 2.3,-2.425 3.5,-2.425
  region: 3.5,-1.475 2.3,-1.475 2.3,-1.775 3.5,-1.775
  rectangle: -3.5,-1.775 -2.3,-1.475
  rectangle: -3.5,-2.425 -2.3,-2.125
  rectangle: -3.5,-3.075 -2.3,-2.775
  rectangle: -3.5,-1.125 -2.3,-0.825
  rectangle: -3.5,-0.475 -2.3,-0.175
  rectangle: -3.5,0.175 -2.3,0.475
  rectangle: -3.5,0.825 -2.3,1.125
  rectangle: -3.5,1.475 -2.3,1.775
  rectangle: -3.5,2.125 -2.3,2.425
  rectangle: -3.5,2.775 -2.3,3.075
  region: 3.5,3.075 2.3,3.075 2.3,2.775 3.5,2.775
  region: 3.5,2.425 2.3,2.425 2.3,2.125 3.5,2.125
  region: 3.5,1.775 2.3,1.775 2.3,1.475 3.5,1.475
  region: 3.5,1.125 2.3,1.125 2.3,0.825 3.5,0.825
  region: 3.5,0.475 2.3,0.475 2.3,0.175 3.5,0.175
  region: 3.5,-0.175 2.3,-0.175 2.3,-0.475 3.5,-0.475
  region: 3.5,-0.825 2.3,-0.825 2.3,-1.125 3.5,-1.125
13 - 3D Top Side:
  circle w0.1: c-1.3,2.35 r0.5
  lines w0.076: -2.25,-3.3 2.25,-3.3 2.25,3.3 -2.25,3.3 -2.25,-3.3
15 - Top Courtyards:
  lines w0.076: -1,0 -0.5,0 ; 0,-1 0,-0.5 ; 0,0.5 0,1 ; 0.5,0 1,0 ; -4,-3.55 4,-3.55 4,3.55 -4,3.55 -4,-3.55
3D body "TSSOP65P640X120-20N.STEP": height 1.2, standoff 0, extent -3.2,-3.25 3.2,3.25

## USB_Micro-B_FCI_SMD [mm]
height 2.286
pads (12):
  round 0.508 on Mech15: 0(0,0)
  rrect20% 0.35x1.5 smd: 1(-1.3,5.6) 2(-0.65,5.6) 3(0,5.6) 4(0.65,5.6) 5(1.3,5.6)
  rrect50% 1.6x2.4 hole 0.8 slot 1.5 at 90 deg: SH(-5.1,1.6) SH(-5.1,5.3) SH(5.1,1.6) SH(5.1,5.3)
  rrect20% 1.2x1.5 smd: SH(-2.35,5.6) SH(2.35,5.6)
Top Solder:
  region: 1.905,4.826 1.905,6.35 -1.905,6.35 -1.905,4.826
Keep-Out Layer:
  board cut-out: -3.9,0 -3.9,3.797 -3.9,3.875 -3.869,4.03 -3.809,4.175 -3.721,4.307 -3.61,4.418 -3.479,4.505 -3.333,4.566 -3.179,4.597 -3.1,4.597 3.1,4.597 3.179,4.597 3.333,4.566 3.479,4.505 3.61,4.418 3.721,4.307 3.809,4.175 3.869,4.03 3.9,3.875 3.9,3.797 3.9,0
13 - 3D Top Side:
  lines w0.127: -4.85,1.1 -4.85,2.1 ; -4.85,4.8 -4.85,5.8 ; -3.97,-0.881 -3.71,-1.031 ; -3.85,1.1 -3.85,2.1 ; -3.85,4.8 -3.85,5.8 ; -3.75,1.1 -5.25,1.1 -5.25,2.1 -3.75,2.1 ; -3.75,4.8 -5.25,4.8 -5.25,5.8 -2.577,5.8 cw(c-2.577,5.6) -2.443,5.748 -2.007,5.352 ccw(c-1.873,5.5) -1.873,5.3 1.873,5.3 ccw(c1.873,5.5) 2.007,5.352 2.443,5.748 cw(c2.577,5.6) 2.577,5.8 5.25,5.8 5.25,4.8 3.75,4.8 ; -3.75,5.8 -3.75,-0.5 ; -3.45,-0.5 cw(c-3.75,-0.501) -3.49,-0.651 -3.76,-1.118 -4.02,-0.968 -3.75,-0.5 ; -3.35,-0.5 -3.35,5.8 ; -3.1,-0.881 ccw(c-3.006,-0.874) -3,-0.968 ; -2.526,5.793 -2.526,5.8 ; -2.229,5.553 ccw(c-2.275,5.8) -2.024,5.8 -1.825,5.8 -1.825,5.3 ; -1.425,5.3 -1.425,5.8 -1.175,5.8 -1.175,5.3 ; -0.775,5.3 -0.775,5.8 -0.525,5.8 -0.525,5.3 ; -0.125,5.3 -0.125,5.8 0.125,5.8 0.125,5.3 ; 0.525,5.3 0.525,5.8 0.775,5.8 0.775,5.3 ; 1.175,5.3 1.175,5.8 1.425,5.8 1.425,5.3 ; 1.825,5.3 1.825,5.8 2.024,5.8 ccw(c2.275,5.8) 2.229,5.553 ; 2.526,5.793 2.526,5.8 ; 3.1,-0.881 cw(c3.006,-0.874) 3,-0.968 ; 3.35,-0.5 3.35,5.8 ; 3.45,-0.5 ccw(c3.75,-0.501) 3.49,-0.651 3.76,-1.118 4.02,-0.968 3.75,-0.5 ; 3.71,-1.031 3.97,-0.881 ; 3.75,1.1 5.25,1.1 5.25,2.1 3.75,2.1 ; 3.75,5.8 3.75,-0.5 ; 3.85,1.1 3.85,2.1 ; 3.85,4.8 3.85,5.8 ; 4.85,1.1 4.85,2.1 ; 4.85,4.8 4.85,5.8 ; -3.75,-0.5 -3.1,-0.5 ; -3.1,-0.5 3.1,-0.501 ; -3.1,-0.5 -3.1,-1.031 ccw(c-3.006,-1.024) -3,-1.118 ; -3,-1.118 3,-1.118 ; -3,-1.118 -3,-0.968 ; -3,-0.968 3,-0.968 ; 3,-1.118 ccw(c3.006,-1.024) 3.1,-1.031 3.1,-0.5 ; 3,-1.118 3,-0.968 ; 3.1,-0.5 3.75,-0.5
15 - Top Courtyards:
  lines w0.076: -6.223,-1.397 -6.223,6.858 6.223,6.858 6.223,-1.397 -6.223,-1.397
  lines w0.127: -3.9,0 -3.9,3.797 cw(c-3.1,3.797) -3.1,4.597 3.1,4.597 cw(c3.1,3.797) 3.9,3.797 3.9,0
3D body "Micro USB B-type mid-mount FCI.STEP": height 2.15, standoff -0.92, extent -5.25,-1.118 5.25,5.8
3D body "USB Micro B plug.STEP": height 4.67, standoff -3.53, extent -5.35,-21.579 5.35,2.921

## USB_Micro-B_Molex_SMD [mm]
height 1.2
pads (12):
  round 0.508 on Mech15: 0(0,0)
  rrect20% 1.25x0.4 smd: 1(6.475,1.3) 2(6.475,0.65) 3(6.475,0) 4(6.475,-0.65) 5(6.475,-1.3)
  rrect20% 2.5x1.5 smd: SH(1.95,-5.15) SH(1.95,5.15) SH(6.15,-5.15) SH(6.15,5.15)
  rrect20% 1.5x2.5 smd: SH(8.35,-2.2) SH(8.35,2.2)
Top Solder:
  rectangle: 5.842,-1.27 7.112,1.27
Keep-Out Layer:
  board cut-out: -0.127,3.9 4.8,3.9 4.879,3.9 5.033,3.869 5.179,3.809 5.31,3.721 5.421,3.61 5.509,3.479 5.569,3.333 5.6,3.179 5.6,3.1 5.6,-3.1 5.6,-3.179 5.569,-3.333 5.509,-3.479 5.421,-3.61 5.31,-3.721 5.179,-3.809 5.033,-3.869 4.879,-3.9 4.8,-3.9 -0.127,-3.9
13 - 3D Top Side:
  lines w0.127: 0,-3.9 4.8,-3.9 ccw(c4.8,-3.1) 5.6,-3.1 5.6,3.1 ccw(c4.8,3.1) 4.8,3.9 0,3.9
15 - Top Courtyards:
  lines w0.076: -0.5,-6.223 -0.5,6.223 9.398,6.223 9.398,-6.223 -0.5,-6.223
3D body "USB Micro B plug.STEP": height 4.1, standoff -4.1, extent -21.007,-5.35 3.492,5.35
3D body "Micro USB B Receptacle Middle Mount.STEP": height 1.43, standoff -1.52, extent -0.43,-5.5 8.7,5.5

## USB_Mini-B_Molex_SMT [mm]
height 3.95
pads (11):
  rrect25% 2.25x0.5 smd: 1(8.25,6.55) 2(8.25,5.75) 3(8.25,4.95) 4(8.25,4.15) 5(8.25,3.35)
  round 0.9 hole 0.9 unplated: H1(6,7.15) H2(6,2.75)
  rrect25% 4x2.05 smd: MH1(4,0.55) MH4(4,9.35)
  rrect25% 3.5x2.05 smd: MH2(8.25,0.55) MH3(8.25,9.35)
Top Overlay:
  lines w0.127: 1.5,1.1 0,1.1 0,9 1.5,9 ; 9,2 10,2 10,8 9,8
15 - Top Courtyards:
  lines w0.076: 0,-0.75 10.275,-0.75 10.275,10.65 0,10.65 0,-0.75
3D body: height 3.95, standoff 0, extent 0,1.1 9,9

## WPAK(3F) [mm] "Footprint similar to SOIC-8, Body 5.1x6.1mm, Pitch 1.27mm, IPC Medium Density"
height 0.85
pads (8):
  round 1 on Mech15: 0(0,0)
  rrect10% 3.1x4.57 smd: D(0.1,0)
  rrect20% 1.47x2.03 smd: D(2.785,-1.27) D(2.785,1.27)
  rrect20% 1.22x0.76 smd: G(-2.91,-1.905) S(-2.91,-0.635) S(-2.91,0.635) S(-2.91,1.905)
Top Overlay:
  circle w0.25: c-2.7,2.7 r0.125
  lines w0.127: 1.6,-2.6 -1.9,-2.6 -1.9,2.6 1.6,2.6
13 - 3D Top Side:
  circle w0.05: c-2.298,1.798 r0.25
  lines w0.05: -3.09,-2.115 -3.09,-2.64 -0.7,-2.64 ; -3.09,-1.695 -3.09,-0.845 ; -3.09,-0.425 -3.09,0.425 ; -3.09,0.845 -3.09,1.695 ; -3.09,2.115 -3.09,2.64 0.5,2.64 ; -3,-2.115 -3,-2.5 ; -3,-1.695 -3,-0.845 ; -3,-0.425 -3,0.425 ; -3,0.845 -3,1.695 ; -3,2.115 -3,2.5 ; -0.7,-2.5 -3,-2.5 ; -0.5,-2.64 3.09,-2.64 3.09,-2.115 ; -0.5,-2.5 3,-2.5 ; 0.5,2.5 -3,2.5 ; 0.7,2.5 3,2.5 ; 0.7,2.64 3.09,2.64 3.09,2.115 ; 3,-2.115 3,-2.5 ; 3,-1.695 3,-0.845 ; 3,-0.425 3,0.425 ; 3,0.845 3,1.695 ; 3,2.115 3,2.5 ; 3.09,-1.695 3.09,-0.845 ; 3.09,-0.425 3.09,0.425 ; 3.09,0.845 3.09,1.695 ; -3,-2.5 -2.864,-2.364 ; -3,2.5 -2.864,2.364 ; -2.864,-2.364 2.864,-2.364 ; -2.864,-2.364 -2.864,2.364 ; -2.864,2.364 2.864,2.364 ; 2.864,-2.364 2.864,2.364 ; 2.864,-2.364 3,-2.5 ; 2.864,2.364 3,2.5 ; -3.1,-2.115 -2.998,-2.115 -2.998,-1.695 -3.1,-1.695 -3.1,-2.115 ; -3.1,-0.845 -2.998,-0.845 -2.998,-0.425 -3.1,-0.425 -3.1,-0.845 ; -3.1,0.425 -2.998,0.425 -2.998,0.845 -3.1,0.845 -3.1,0.425 ; -3.1,1.695 -2.998,1.695 -2.998,2.115 -3.1,2.115 -3.1,1.695 ; -0.7,-2.65 -0.7,-2.498 -0.5,-2.498 -0.5,-2.65 -0.7,-2.65 ; 0.5,2.498 0.5,2.65 0.7,2.65 0.7,2.498 0.5,2.498 ; 2.998,-2.115 3.1,-2.115 3.1,-1.695 2.998,-1.695 2.998,-2.115 ; 2.998,-0.845 3.1,-0.845 3.1,-0.425 2.998,-0.425 2.998,-0.845 ; 2.998,0.425 3.1,0.425 3.1,0.845 2.998,0.845 2.998,0.425 ; 2.998,1.695 3.1,1.695 3.1,2.115 2.998,2.115 2.998,1.695
15 - Top Courtyards:
  lines w0.076: -3.7,-2.65 3.7,-2.65 3.7,2.65 -3.7,2.65 -3.7,-2.65
3D body "WPAK(3F).STEP": height 0.85, standoff 0, extent -3.1,-2.65 3.1,2.65

## ZIF_CONN_4P_TE84953-4 [mm] "TE Connectivity 4-pin ZIF connector"
height 2.74
pads (7):
  round 0.5 on Mech15: 0(0,0)
  rrect25% 0.61x2 smd: 1(-1.5,5.375) 2(-0.5,5.375) 3(0.5,5.375) 4(1.5,5.375)
  rrect25% 2.7x3.6 smd: MH(-4.5,2.6) MH(4.5,2.6)
13 - 3D Top Side:
  lines w0.05: -4.56,3.1 -3.93,3.1 ; -4.56,4.37 -4.56,0.87 -3.67,0.87 -3.67,0 ; -4.28,4.37 -4.18,3.997 -4.18,3.1 ; -4.18,0.86 -4.18,0.87 ; -3.982,0.87 -3.982,0.86 -5.072,0.86 cw(c-5.072,0.96) -5.172,0.96 -5.172,1.261 cw(c-5.072,1.261) -5.072,1.361 -4.762,1.361 ccw(c-4.762,1.461) -4.662,1.461 -4.662,1.763 ccw(c-4.762,1.763) -4.762,1.863 -5.072,1.863 cw(c-5.072,1.963) -5.172,1.963 -5.172,2.264 cw(c-5.072,2.264) -5.072,2.364 -4.762,2.364 ccw(c-4.762,2.464) -4.662,2.464 -4.662,2.766 ccw(c-4.762,2.766) -4.762,2.866 -5.072,2.866 cw(c-5.072,2.966) -5.172,2.966 -5.172,3.267 cw(c-5.072,3.267) -5.072,3.367 -4.762,3.367 ccw(c-4.762,3.467) -4.662,3.467 -4.662,3.769 ccw(c-4.762,3.769) -4.762,3.869 -5.072,3.869 cw(c-5.072,3.969) -5.172,3.969 -5.172,4.27 cw(c-5.072,4.27) -5.072,4.37 5.072,4.37 cw(c5.072,4.27) 5.172,4.27 5.172,3.969 cw(c5.072,3.969) 5.072,3.869 4.762,3.869 ccw(c4.762,3.769) 4.662,3.769 4.662,3.467 ccw(c4.762,3.467) 4.762,3.367 5.072,3.367 cw(c5.072,3.267) 5.172,3.267 5.172,2.966 cw(c5.072,2.966) 5.072,2.866 4.762,2.866 ccw(c4.762,2.766) 4.662,2.766 4.662,2.464 ccw(c4.762,2.464) 4.762,2.364 5.072,2.364 cw(c5.072,2.264) 5.172,2.264 5.172,1.963 cw(c5.072,1.963) 5.072,1.863 4.762,1.863 ccw(c4.762,1.763) 4.662,1.763 4.662,1.461 ccw(c4.762,1.461) 4.762,1.361 5.072,1.361 cw(c5.072,1.261) 5.172,1.261 5.172,0.96 cw(c5.072,0.96) 5.072,0.86 4.232,0.86 4.229,0.87 ; -3.93,0.87 -3.93,3.997 -3.83,4.37 ; -3.846,0.79 -3.75,0.43 -3.75,0 3.55,0 3.55,0.43 3.646,0.79 ; -3.67,0.79 -4.94,0.79 -4.94,0.39 ccw(c-4.76,0.39) -4.76,0.21 cw(c-4.76,0.03) -4.76,-0.15 -5.96,-0.15 -5.96,-1.04 5.96,-1.04 5.96,-0.15 4.76,-0.15 cw(c4.76,0.03) 4.76,0.21 ccw(c4.76,0.39) 4.94,0.39 4.94,0.79 3.47,0.79 ; -2.82,-1.04 -2.59,0 ; -2.311,0 -2.311,-0.63 -1.691,-0.63 -1.691,0 ; -1.596,4.37 -1.596,5.51 -1.396,5.51 -1.396,4.37 ; -1.596,4.88 -1.396,4.88 ; -1.596,5.01 -1.396,5.01 ; -1.596,5.38 -1.396,5.38 ; -1.311,0 -1.311,-0.63 -0.691,-0.63 -0.691,0 ; -0.596,4.37 -0.596,5.51 -0.396,5.51 -0.396,4.37 ; -0.596,4.88 -0.396,4.88 ; -0.596,5.01 -0.396,5.01 ; -0.596,5.38 -0.396,5.38 ; -0.31,0 -0.31,-0.63 0.309,-0.63 0.309,0 ; 0.405,4.37 0.405,5.51 0.604,5.51 0.604,4.37 ; 0.405,4.88 0.604,4.88 ; 0.405,5.01 0.604,5.01 ; 0.405,5.38 0.604,5.38 ; 0.69,0 0.69,-0.63 1.309,-0.63 1.309,0 ; 1.405,4.37 1.405,5.51 1.605,5.51 1.605,4.37 ; 1.405,4.88 1.605,4.88 ; 1.405,5.01 1.605,5.01 ; 1.405,5.38 1.605,5.38 ; 1.69,0 1.69,-0.63 2.31,-0.63 2.31,0 ; 2.59,0 2.82,-1.04 ; 3.47,0 3.47,0.87 4.56,0.87 4.56,4.37 ; 3.83,0.87 3.93,1.243 3.93,4.37 ; 3.93,2.14 4.18,2.14 4.18,1.243 4.28,0.87 ; 4.18,1.92 4.56,1.92 ; -1.871,0.87 -1.111,0.87 -1.49,0.11 -1.871,0.87
15 - Top Courtyards:
  lines w0.127: -6.1,-1.2 -6.1,5.7 -2.1,5.7 -2.1,6.7 2.1,6.7 2.1,5.7 6.2,5.7 6.2,-1.2 -6.1,-1.2
3D body "ZIF Conn TE 84953-4.STEP": height 2.58, standoff 0, extent -5.96,-1.04 5.96,5.51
